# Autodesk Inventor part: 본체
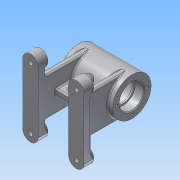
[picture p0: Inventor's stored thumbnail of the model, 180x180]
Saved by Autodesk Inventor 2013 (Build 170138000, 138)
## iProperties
Created: 2015-11
Part Number: 본체
Material: 알루미늄 6061
Document SubType Name: Modeling
Designer: Administrator
Density: 2.71 g/cm^3
Mass: 359.088 g
Surface Area: 459.697 cm^2
Volume: 132.505 cm^3
Author: Administrator
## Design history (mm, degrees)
sketch "스케치1"
  geometry: L1 (-35, 25)-(0, 25); L2 (0, 25)-(0, 0); L3 (0, 0)-(-35, 0); L4 (-35, 0)-(-35, 25); L5 (-35, 16)-(-23, 16); L6 (-23, 16)-(-23, 14); L7 (-23, 14)-(-21, 14); L8 (-21, 14)-(-21, 21); L9 (-21, 21)-(0, 21); 1 further point
  constraints: 18 end point, 4 parallel, 4 perpendicular, 2 point on line, 1 coincident, 1 horizontal
  dimensions: "d0" = 35 distance of L2.end L3.end; "d1" = 25 distance of L1.end L2.end; "d2" = 32 diameter of L5 L3; "d3" = 28 diameter of L7 L3; "d4" = 42 diameter of L9 L3; "d5" = 2 distance between parallel lines of L6 L8; "d6" = 12 distance of L5.start L5.end
revolve "회전1" sketch "스케치1" stored, may be unused: angle "d7" = 90 deg
fillet "모깎기1" dims "d8" = 0.3
fillet "모깎기2" dims "d9" = 3
chamfer "모따기1" distance "d10" = 1; stored, may be unused: second distance "d11" = 2, angle "d12" = 45 deg
sketch "스케치2"
  geometry: C1 r 25 at (0, 0) reference; 1 further point
  constraints: 1 vertical alignment
  dimensions: "d13" = 20 distance of C1.centre point (0, 20)
hole "구멍1" sketch "스케치2" at (0, 20) diameter "d14" = 3.242; stored, may be unused: countersink angle "d18" = 90 deg, drill point angle "d20" = 118 deg; dims "d15" = 8, "d16" = 4, "d17" = 2, "d19" = 10
node "작업 평면1"
sketch "스케치3"
  geometry: C1 r 5 at (0, 0); 1 further point
  constraints: 1 centre point, 1 coincident
  dimensions: "d25" = 10 diameter of C1
extrude "돌출1" join sketch "스케치3" stored distance "d26" = 10 (= d25); taper "d27" = 0 deg
hole "구멍2" diameter "d30" = 5.188; stored, may be unused: countersink angle "d34" = 90 deg, drill point angle "d36" = 118 deg; dims "d31" = 28, "d32" = 4, "d33" = 2, "d35" = 28, "d75" = 10, "d76" = 10
sketch "스케치4"
  geometry: L1 (0, 0)-(-24.249, 14); L2 (0, 0)-(28, 0)
  constraints: 4 end point, 1 equal length, 1 horizontal
  dimensions: "d37" = 28 distance of L1.start L1.end; "d38" = 150 deg angle of L2 L1
node "작업 평면2"
sketch "스케치5"
  geometry: C1 r 6 at (0, 0); 1 further point
  constraints: 1 centre point, 1 coincident
  dimensions: "d39" = 12 diameter of C1
extrude "돌출2" join sketch "스케치5" stored distance "d40" = 10; taper "d41" = 0 deg
hole "구멍3" diameter "d44" = 5.188; stored, may be unused: countersink angle "d48" = 90 deg, drill point angle "d50" = 118 deg; dims "d45" = 28, "d46" = 4, "d47" = 2, "d49" = 28, "d77" = 10, "d78" = 10
node "작업 평면3"
sketch "스케치7"
  geometry: L1 (58, -50)-(68, -50); L2 (68, -50)-(68, 50); L3 (68, 50)-(58, 50); L4 (58, 50)-(58, -50); 2 further points
  constraints: 8 end point, 2 parallel, 1 horizontal, 1 horizontal alignment, 1 midpoint, 1 perpendicular
  dimensions: "d52" = 10 distance of L3.end L2.end; "d53" = 100 distance of L2.end L1.end; "d54" = 68 distance from line of point (0, 0) L2
extrude "돌출3" join sketch "스케치7" distance "d55" = 20; taper "d56" = 0 deg
fillet "모깎기3" dims "d57" = 10
sketch "스케치8"
  geometry: C1 r 10 at (10, 80); C2 r 10 at (10, 0); A1 r 10 centre (10, 80) between (20, 80) and (0, 80) reference; A2 r 10 centre (10, 0) between (0, 0) and (20, 0) reference; 1 further point
  constraints: 2 centre point, 2 coincident
  dimensions: "d58" = 20 diameter of C1; "d59" = 20 diameter of C2
extrude "돌출4" join sketch "스케치8" distance "d60" = 3; taper "d61" = 0 deg
hole "구멍4" diameter "d64" = 6; stored, may be unused: countersink angle "d68" = 90 deg, drill point angle "d70" = 0 deg; dims "d62" = 10, "d63" = 10, "d65" = 28, "d66" = 12, "d67" = 4, "d69" = 30
fillet "모깎기4" dims "d71" = 0.3
chamfer "모따기2" distance "d72" = 1; stored, may be unused: second distance "d73" = 2, angle "d74" = 45 deg
sketch "스케치9"
  geometry: L1 (20, 80)-(20, 0) reference; L2 (20, 65)-(12, 65); L3 (12, 65)-(12, 15); L4 (12, 15)-(20, 15); L5 (20, 15)-(20, 65); 2 further points
  constraints: 8 end point, 2 midpoint, 2 parallel, 1 horizontal, 1 perpendicular
  dimensions: "d79" = 8 distance of L4.end L3.end; "d80" = 50 distance of L3.end L2.end
extrude "돌출5" join sketch "스케치9" stored distance "d81" = 3; taper "d82" = 0 deg
node "작업 평면4"
sketch "스케치11"
  geometry: L1 (-20, 4)-(20, 4); L2 (20, 4)-(20, -4); L3 (20, -4)-(-20, -4); L4 (-20, -4)-(-20, 4); L5 (-28, 25)-(-20, 25) reference; L6 (-20, 25)-(-20, -25) reference; L7 (-20, -25)-(-28, -25) reference; L8 (-28, -25)-(-28, 25) reference; L9 (20, 25)-(28, 25) reference; L10 (28, 25)-(28, -25) reference; L11 (28, -25)-(20, -25) reference; L12 (20, -25)-(20, 25) reference; 2 further points
  constraints: 8 end point, 2 midpoint, 2 parallel, 1 horizontal, 1 perpendicular
  dimensions: "d84" = 40 distance of L2.end L3.end; "d85" = 8 distance of L1.end L2.end
extrude "돌출6" join sketch "스케치11" stored distance "d86" = 3; taper "d87" = 0 deg
sketch "스케치12"
  geometry: L1 (8.5, 13.5)-(31.5, 13.5); L2 (31.5, 13.5)-(31.5, 6.5); L3 (31.5, 6.5)-(8.5, 6.5); L4 (8.5, 6.5)-(8.5, 13.5); L5 (8.5, 13.5)-(31.5, 6.5); L6 (31.5, 13.5)-(8.5, 6.5); L7 (40, -23)-(60, -23) reference; 2 further points
  constraints: 12 end point, 2 midpoint, 2 parallel, 1 horizontal, 1 perpendicular
  dimensions: "d88" = 23 distance of L2.end L3.end; "d89" = 7 distance of L1.end L2.end; "d90" = 11.5 distance from line of L4 point (20, 45); "d91" = 33 distance from line of L7 point (20, 10)
extrude "돌출7" cut sketch "스케치12" stored distance "d92" = 3; taper "d93" = 0 deg
fillet "모깎기5" dims "d94" = 3.5
node "작업 평면5"
sketch "스케치13"
  geometry: L1 (2.5, -68)-(2.5, -58) reference; L2 (2.5, -58)-(2.5, 0) reference; L3 (2.5, 0)-(-37.5, 0) reference; L4 (-37.5, 0)-(-37.5, -58) reference; L5 (-37.5, -58)-(-37.5, -68) reference; L6 (-37.5, -68)-(-57.5, -68) reference; L7 (-57.5, -68)-(-57.5, -58) reference; L8 (-57.5, -58)-(-45.5, -58) reference; L9 (-45.5, -58)-(-37.5, -58) reference; L10 (22.5, -68)-(2.5, -68) reference; L11 (22.5, -58)-(22.5, -68) reference; L12 (10.5, -58)-(22.5, -58) reference; L13 (2.5, -58)-(10.5, -58) reference; L14 (10.5, 0)-(2.5, 0) reference; L15 (17.5, 0)-(10.5, 0) reference; L16 (-37.5, 0)-(-45.5, 0) reference; L17 (-45.5, 0)-(-52.5, 0) reference; L18 (-45.5, -58)-(-45.5, 0) reference; L19 (10.5, 0)-(10.5, -58) reference; L20 (17.5, 25)-(-52.5, 25) reference; L21 (-52.5, 25)-(-52.5, -25) reference; 2 further points
  constraints: 1 other
  dimensions: "d99" = 25 distance from line of point (-17.5, 0) L20; "d100" = 35 distance from line of point (-17.5, 0) L21
feature "엠보싱1" sketch "스케치13" dims "d11" = 2, "d101" = 0.5, "d102" = 0
fillet "모깎기11" dims "d104" = 2
fillet "모깎기12" dims "d105" = 2
node "솔리드1"
pattern_circular "원형 패턴1" dims angle "d22" = 360 deg
mirror "대칭1"
mirror "대칭2"
mirror "대칭3"
node "절단 모서리 투영3"
node "절단 모서리 투영4"
other parameters: "d24" = 28, "d83" = -45
